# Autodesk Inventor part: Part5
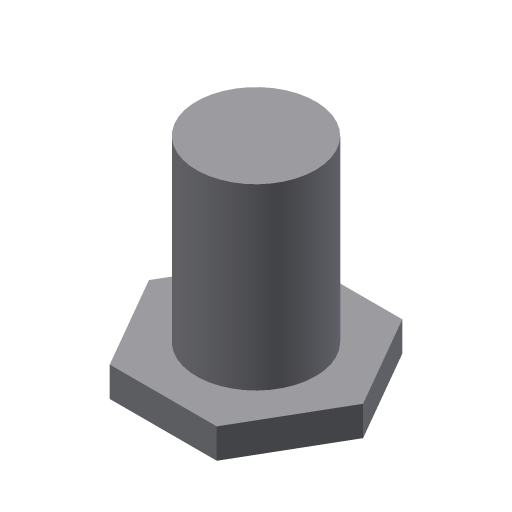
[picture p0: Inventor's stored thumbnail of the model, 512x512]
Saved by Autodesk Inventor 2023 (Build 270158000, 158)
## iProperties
Created: 2008-05
Part Number: Part5
Document SubType Name: Modeling
Designer: CADCIM
Density: 1 g/cm^3
Material: Generic
Appearance: Default
Author: CADCIM
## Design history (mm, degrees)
sketch "Sketch1"
  geometry: C1 r 2 at (-7.12, 11.618)
  constraints: 1 centre point
  dimensions: "d2" = 4 diameter of C1
extrude "Extrusion1" new body sketch "Sketch1" distance "d0" = 6; taper "d1" = 0 deg
sketch "Sketch2"
  geometry: L1 (-3.598, 0)-(-1.799, 3.116); L2 (-1.799, 3.116)-(1.799, 3.116); L3 (1.799, 3.116)-(3.598, 0); L4 (3.598, 0)-(1.799, -3.116); L5 (1.799, -3.116)-(-1.799, -3.116); L6 (-1.799, -3.116)-(-3.598, 0); C1 r 2 at (0, 0) reference; 1 further point
  constraints: 12 end point, 1 coincident, 13 other
extrude "Extrusion2" join sketch "Sketch2" distance "d3" = 1; taper "d4" = 0 deg
body "Solid1"
